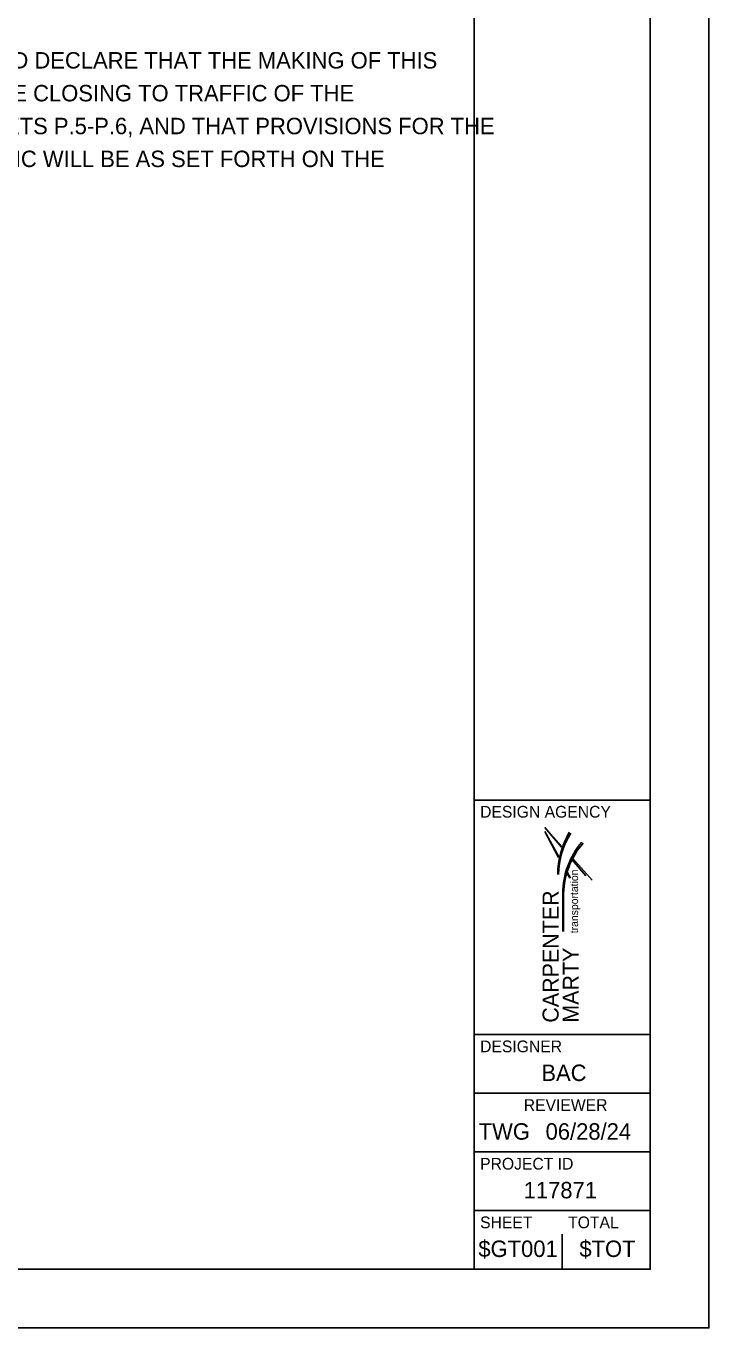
# Model space of a CAD drawing. Extents: x 0 to 34, y 0 to 22.
# Drawn here: x 28.18 to 34, y 0 to 11.1 of the extents above; entities that cross this region are included whole.
import ezdxf

# ---------------------------------------------------------------- set-up
doc = ezdxf.new("R2010")
doc.units = 0
for name, color, linetype in [('SH_Border', 7, 'Continuous'), ('SH_Cut_Line', 7, 'Continuous'), ('SH_Data', 7, 'Continuous'), ('SH_Text', 7, 'Continuous')]:
    doc.layers.add(name, color=color, linetype=linetype)

msp = doc.modelspace()

# ---------------------------------------------------------------- linework, layer by layer
at = {"layer": 'SH_Border'}
for p, q in [((32, 0.5), (32, 21.5)), ((32, 4.5), (33.5, 4.5)), ((32, 2.5), (33.5, 2.5)), ((32, 2), (33.5, 2)), ((32, 1.5), (33.5, 1.5)), ((32, 1), (33.5, 1))]:
    msp.add_line(p, q, dxfattribs=at)
msp.add_lwpolyline([(1.5, 21.5), (33.5, 21.5), (33.5, 0.5), (1.5, 0.5)], close=True, dxfattribs=at)
at = {"layer": 'SH_Cut_Line'}
msp.add_lwpolyline([(0, 0), (34, 0), (34, 22), (0, 22)], close=True, dxfattribs=at)
at = {"layer": 'SH_Data'}
for p, q in [((32.75, 3.5), (32.75, 3.5)), ((32.75, 0.5), (32.75, 0.8)), ((32.375, 0.675), (32.375, 0.675))]:
    msp.add_line(p, q, dxfattribs=at)
at = {"layer": 'SH_Text'}
for p, q in [((32.721, 4.016), (32.602, 4.232)), ((32.839, 4.002), (33.006, 3.816)), ((32.82, 3.834), (32.791, 3.886)), ((32.952, 3.853), (32.834, 3.991)), ((32.811, 3.84), (32.79, 3.88)), ((32.755, 3.378), (32.755, 3.704)), ((32.762, 3.378), (32.762, 3.704))]:
    msp.add_line(p, q, dxfattribs=at)
for points in [[(32.746, 4.104), (32.601, 4.266)], [(32.601, 4.266), (32.744, 4.098)], [(32.721, 4.016), (32.602, 4.232)], [(32.602, 4.232), (32.719, 4.011)]]:
    msp.add_lwpolyline(points, dxfattribs=at)
for centre, radius, start, end in [((33.432, 3.86), 0.721, 149.5704, 179.5529), ((33.373, 3.862), 0.654, 147.1423, 179.6525), ((33.426, 3.704), 0.671, 139.2898, 180.0106), ((33.433, 3.688), 0.672, 138.5126, 178.6075)]:
    msp.add_arc(centre, radius, start, end, dxfattribs=at)

# ---------------------------------------------------------------- texts
at = {"layer": 'SH_Data'}
for s, height, p in [(' I HEREBY APPROVE THESE PLANS AND DECLARE THAT THE MAKING OF THIS', 0.14, (24.528, 10.735)), ('IMPROVEMENT WILL NOT REQUIRE THE CLOSING TO TRAFFIC OF THE', 0.14, (24.528, 10.455)), ('HIGHWAY EXCEPT AS NOTED ON SHEETS P.5-P.6, AND THAT PROVISIONS FOR THE', 0.14, (24.528, 10.175)), ('MAINTENANCE AND SAFETY OF TRAFFIC WILL BE AS SET FORTH ON THE', 0.14, (24.528, 9.895)), ('DESIGN AGENCY', 0.1, (32.05, 4.35)), ('DESIGNER', 0.1, (32.05, 2.35)), ('BAC', 0.14, (32.572, 2.105)), ('REVIEWER', 0.1, (32.422, 1.85)), ('TWG', 0.14, (32.038, 1.605)), ('06/28/24', 0.14, (32.608, 1.605)), ('PROJECT ID', 0.1, (32.05, 1.35)), ('117871', 0.14, (32.421, 1.105)), ('SHEET', 0.1, (32.05, 0.85)), ('TOTAL', 0.1, (32.8, 0.85)), ('$GT001', 0.14, (32.035, 0.605)), ('$TOT', 0.14, (32.896, 0.605))]:
    msp.add_text(s, height=height, dxfattribs=at).set_placement(p)
at = {"layer": 'SH_Text'}
for s, height, p in [('transportation', 0.06649, (32.885, 3.364)), ('CARPENTER ', 0.1367, (32.719, 2.602)), ('MARTY', 0.1367, (32.891, 2.602))]:
    msp.add_text(s, height=height, rotation=90, dxfattribs=at).set_placement(p)

doc.saveas('drawing.dxf')
